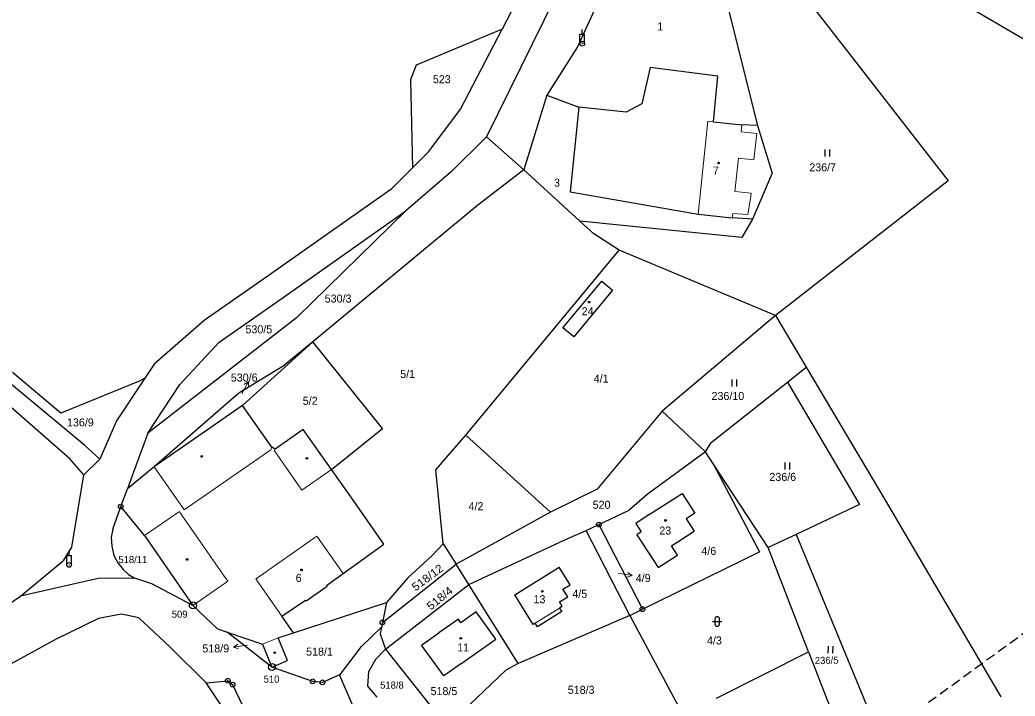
# Model space of a CAD drawing. Extents: x -885985 to -883535, y -1030025 to -1027941.
# Drawn here: x -884740.1 to -884528.7, y -1028443.4 to -1028299.8 of the extents above; entities that cross this region are included whole.
import ezdxf
from ezdxf.enums import TextEntityAlignment as Align

# ---------------------------------------------------------------- set-up
doc = ezdxf.new("R2010")
doc.units = 0
doc.header["$LTSCALE"] = 0.68
doc.linetypes.add('MEDIUM_DASHED', pattern=[4.5, 3, -1.5])
for name, color, linetype, lineweight in [('1', 7, 'Continuous', 25), ('13', 7, 'Continuous', 13), ('3', 7, 'Continuous', 25), ('4', 7, 'Continuous', 13), ('5', 7, 'Continuous', 25), ('6', 7, 'Continuous', 25), ('7', 7, 'Continuous', 13), ('8', 7, 'Continuous', 25)]:
    doc.layers.add(name, color=color, linetype=linetype, lineweight=lineweight)
doc.layers.add('2', color=7, linetype='Continuous')

msp = doc.modelspace()

# ---------------------------------------------------------------- linework, layer by layer
at = {"layer": '1'}
for p, q in [((-884601.9, -1028245.3), (-884640.99, -1028324.69)), ((-884598.34, -1028262.73), (-884542.88, -1028334.03)), ((-884598.34, -1028262.73), (-884583.43, -1028322.24)), ((-884606.99, -1028273.29), (-884621.63, -1028305.56)), ((-884512.54, -1028312.41), (-884580.94, -1028272.18)), ((-884635.61, -1028297.86), (-884637.65, -1028301.77)), ((-884637.65, -1028301.77), (-884655.9, -1028309.42)), ((-884646.51, -1028318.78), (-884637.65, -1028301.77)), ((-884621.63, -1028305.56), (-884628.2, -1028315.79)), ((-884655.9, -1028309.42), (-884657.11, -1028312.58)), ((-884606.23, -1028309.96), (-884607.96, -1028317.68)), ((-884591.81, -1028311.77), (-884606.23, -1028309.96)), ((-884592.79, -1028321.47), (-884591.81, -1028311.77)), ((-884657.11, -1028312.58), (-884656.72, -1028331.28)), ((-884628.2, -1028315.79), (-884633.08, -1028331.68)), ((-884628.2, -1028315.79), (-884621.35, -1028318.39)), ((-884607.96, -1028317.68), (-884611.34, -1028319.41)), ((-884653.26, -1028327.81), (-884646.51, -1028318.78)), ((-884621.35, -1028318.39), (-884623.24, -1028336.34)), ((-884611.34, -1028319.41), (-884621.35, -1028318.39)), ((-884592.79, -1028321.47), (-884586.72, -1028322.11)), ((-884583.43, -1028322.24), (-884586.72, -1028322.11)), ((-884583.43, -1028322.24), (-884580.27, -1028332.36)), ((-884640.99, -1028324.69), (-884648.41, -1028332.02)), ((-884640.99, -1028324.69), (-884633.08, -1028331.68)), ((-884656.72, -1028331.28), (-884653.26, -1028327.81)), ((-884656.72, -1028331.28), (-884661.3, -1028335.88)), ((-884648.41, -1028332.02), (-884658.14, -1028340.41)), ((-884633.08, -1028331.68), (-884642.8, -1028339.2)), ((-884621.16, -1028342.55), (-884633.08, -1028331.68)), ((-884580.27, -1028332.36), (-884584.5, -1028342.13)), ((-884542.88, -1028334.03), (-884577.06, -1028360.62)), ((-884661.3, -1028335.88), (-884687.36, -1028354.22)), ((-884623.24, -1028336.34), (-884596.04, -1028341.08)), ((-884642.8, -1028339.2), (-884677.87, -1028368.19)), ((-884684.16, -1028358.8), (-884658.14, -1028340.41)), ((-884658.14, -1028340.41), (-884681.31, -1028363.1)), ((-884596.04, -1028341.08), (-884588.76, -1028341.86)), ((-884618.17, -1028345.28), (-884621.16, -1028342.55)), ((-884586.71, -1028346.02), (-884621.16, -1028342.55)), ((-884584.5, -1028342.13), (-884588.76, -1028341.86)), ((-884584.5, -1028342.13), (-884586.71, -1028346.02)), ((-884612.79, -1028348.72), (-884618.17, -1028345.28)), ((-884645.35, -1028388.02), (-884612.79, -1028348.72)), ((-884579.61, -1028362.61), (-884612.79, -1028348.72)), ((-884729.52, -1028393.05), (-884772.29, -1028355.57)), ((-884687.36, -1028354.22), (-884700.95, -1028363.68)), ((-884726.38, -1028390.13), (-884763.34, -1028359.63)), ((-884697.76, -1028368.25), (-884684.16, -1028358.8)), ((-884577.06, -1028360.62), (-884579.61, -1028362.61)), ((-884681.31, -1028363.1), (-884712.92, -1028387.6)), ((-884700.95, -1028363.68), (-884711.6, -1028372.97)), ((-884579.61, -1028362.61), (-884603.68, -1028382.96)), ((-884579.61, -1028362.61), (-884573.11, -1028373.62)), ((-884706.14, -1028377.29), (-884697.76, -1028368.25)), ((-884677.87, -1028368.19), (-884692.81, -1028381.71)), ((-884677.87, -1028368.19), (-884684.17, -1028373.4)), ((-884663.05, -1028386.59), (-884677.87, -1028368.19)), ((-884711.6, -1028372.97), (-884713.58, -1028375.93)), ((-884731.39, -1028383.37), (-884741.68, -1028374.7)), ((-884684.17, -1028373.4), (-884693.57, -1028379.12)), ((-884577.07, -1028376.76), (-884573.11, -1028373.62)), ((-884573.11, -1028373.62), (-884556.32, -1028401.83)), ((-884714.57, -1028376.52), (-884731.39, -1028383.37)), ((-884713.58, -1028375.93), (-884719.6, -1028384.95)), ((-884713.58, -1028375.93), (-884714.57, -1028376.52)), ((-884712.92, -1028387.6), (-884706.14, -1028377.29)), ((-884593.29, -1028389.56), (-884577.07, -1028376.76)), ((-884577.07, -1028376.76), (-884561.72, -1028402.78)), ((-884693.57, -1028379.12), (-884711.56, -1028394.75)), ((-884692.81, -1028381.71), (-884711.56, -1028394.75)), ((-884686.56, -1028390.59), (-884692.81, -1028381.71)), ((-884603.68, -1028382.96), (-884617.46, -1028399.52)), ((-884603.68, -1028382.96), (-884594.47, -1028391.59)), ((-884719.6, -1028384.95), (-884723.14, -1028393.15)), ((-884712.92, -1028387.6), (-884715.98, -1028395.85)), ((-884679.9, -1028386.82), (-884685.85, -1028391)), ((-884673.9, -1028395.32), (-884679.9, -1028386.82)), ((-884673.9, -1028395.32), (-884663.05, -1028386.59)), ((-884651.75, -1028395.4), (-884645.35, -1028388.02)), ((-884627.36, -1028404.37), (-884645.35, -1028388.02)), ((-884594.47, -1028391.59), (-884593.29, -1028389.56)), ((-884723.14, -1028393.15), (-884726.38, -1028390.13)), ((-884685.85, -1028391), (-884686.56, -1028390.59)), ((-884594.47, -1028391.59), (-884606.87, -1028400.64)), ((-884592.87, -1028393.98), (-884594.47, -1028391.59)), ((-884726.51, -1028396.43), (-884729.52, -1028393.05)), ((-884726.51, -1028396.43), (-884723.14, -1028393.15)), ((-884592.87, -1028393.98), (-884582.99, -1028412.79)), ((-884581.14, -1028411.9), (-884592.87, -1028393.98)), ((-884711.56, -1028394.75), (-884717.22, -1028399.45)), ((-884715.98, -1028395.85), (-884717.22, -1028399.45)), ((-884669.56, -1028401.43), (-884673.9, -1028395.32)), ((-884650.17, -1028411.13), (-884651.75, -1028395.4)), ((-884729.05, -1028411.79), (-884726.51, -1028396.43)), ((-884718.69, -1028403.2), (-884717.22, -1028399.45)), ((-884617.46, -1028399.52), (-884627.36, -1028404.37)), ((-884606.41, -1028404.89), (-884599.43, -1028400.4)), ((-884599.43, -1028400.4), (-884596.7, -1028404.59)), ((-884662.81, -1028411.16), (-884669.56, -1028401.43)), ((-884606.87, -1028400.64), (-884610.68, -1028403.94)), ((-884556.32, -1028401.83), (-884531.74, -1028443.62)), ((-884720.39, -1028408), (-884718.69, -1028403.2)), ((-884713.65, -1028409.3), (-884718.69, -1028403.2)), ((-884627.36, -1028404.37), (-884647.46, -1028415.4)), ((-884617.1, -1028407), (-884610.68, -1028403.94)), ((-884596.7, -1028404.59), (-884598.57, -1028405.79)), ((-884561.72, -1028402.78), (-884575.21, -1028409.11)), ((-884606.41, -1028404.89), (-884609.29, -1028406.78)), ((-884598.57, -1028405.79), (-884596.87, -1028408.41)), ((-884720.39, -1028408), (-884720.73, -1028409.7)), ((-884624.31, -1028410.29), (-884619.81, -1028408.29)), ((-884619.81, -1028408.29), (-884617.1, -1028407)), ((-884610.56, -1028426.3), (-884619.81, -1028408.29)), ((-884617.1, -1028407), (-884607.86, -1028424.98)), ((-884601.68, -1028411.55), (-884596.87, -1028408.41)), ((-884720.73, -1028409.7), (-884720.6, -1028411.62)), ((-884713.65, -1028409.3), (-884703.35, -1028424.17)), ((-884671.43, -1028417.39), (-884662.81, -1028411.16)), ((-884650.17, -1028411.13), (-884652.63, -1028413.64)), ((-884650.17, -1028411.13), (-884647.46, -1028415.4)), ((-884644.72, -1028419.71), (-884624.31, -1028410.29)), ((-884609.02, -1028409.16), (-884604.48, -1028416.15)), ((-884575.21, -1028409.11), (-884581.14, -1028411.9)), ((-884575.21, -1028409.11), (-884553.2, -1028462.33)), ((-884730.78, -1028414.56), (-884729.05, -1028411.79)), ((-884720.6, -1028411.62), (-884720.17, -1028413.58)), ((-884607.86, -1028424.98), (-884582.99, -1028412.79)), ((-884600.42, -1028413.5), (-884601.68, -1028411.55)), ((-884572.61, -1028434.07), (-884581.14, -1028411.9)), ((-884739.96, -1028422.25), (-884730.78, -1028414.56)), ((-884720.17, -1028413.58), (-884719.3, -1028415.16)), ((-884719.3, -1028415.16), (-884718.16, -1028416.55)), ((-884663.08, -1028427.79), (-884647.46, -1028415.4)), ((-884652.63, -1028413.64), (-884657.67, -1028418.33)), ((-884644.72, -1028419.71), (-884647.46, -1028415.4)), ((-884604.48, -1028416.15), (-884600.42, -1028413.5)), ((-884718.16, -1028416.55), (-884717.04, -1028417.61)), ((-884674.99, -1028419.92), (-884671.43, -1028417.39)), ((-884634.99, -1028421.96), (-884625.53, -1028416.09)), ((-884623.24, -1028419.78), (-884625.53, -1028416.09)), ((-884723.5, -1028418.44), (-884739.96, -1028422.25)), ((-884715.7, -1028418.43), (-884723.5, -1028418.44)), ((-884717.04, -1028417.61), (-884715.7, -1028418.43)), ((-884712.1, -1028419.58), (-884715.7, -1028418.43)), ((-884703.35, -1028424.17), (-884712.1, -1028419.58)), ((-884657.67, -1028418.33), (-884662.22, -1028423.53)), ((-884679.31, -1028423.19), (-884674.84, -1028420.07)), ((-884674.84, -1028420.07), (-884674.99, -1028419.92)), ((-884662.42, -1028433.46), (-884644.72, -1028419.71)), ((-884634.26, -1028436.55), (-884644.72, -1028419.71)), ((-884624.75, -1028420.72), (-884623.24, -1028419.78)), ((-884623.72, -1028422.36), (-884624.75, -1028420.72)), ((-884750, -1028428.98), (-884739.96, -1028422.25)), ((-884684.45, -1028426.49), (-884679.42, -1028423.04)), ((-884681.98, -1028430.02), (-884662.22, -1028423.53)), ((-884679.42, -1028423.04), (-884679.31, -1028423.19)), ((-884631.04, -1028428.22), (-884634.99, -1028421.96)), ((-884625.46, -1028423.45), (-884623.72, -1028422.36)), ((-884624.88, -1028424.38), (-884625.46, -1028423.45)), ((-884703.35, -1028424.17), (-884698.1, -1028429.13)), ((-884643.17, -1028425.52), (-884646.46, -1028427.89)), ((-884639, -1028431.37), (-884643.17, -1028425.52)), ((-884624.98, -1028425.5), (-884630.13, -1028428.72)), ((-884624.88, -1028424.38), (-884625.45, -1028424.74)), ((-884625.45, -1028424.74), (-884624.98, -1028425.5)), ((-884610.56, -1028426.3), (-884607.86, -1028424.98)), ((-884723.41, -1028426.93), (-884732.52, -1028431.41)), ((-884718.51, -1028426.06), (-884723.41, -1028426.93)), ((-884714.87, -1028426.79), (-884718.51, -1028426.06)), ((-884708.28, -1028433), (-884714.87, -1028426.79)), ((-884681.98, -1028430.02), (-884684.45, -1028426.49)), ((-884646.96, -1028427.11), (-884651.09, -1028430.02)), ((-884646.46, -1028427.89), (-884646.96, -1028427.11)), ((-884610.56, -1028426.3), (-884634.26, -1028436.55)), ((-884630.61, -1028427.95), (-884631.04, -1028428.22)), ((-884630.13, -1028428.72), (-884630.61, -1028427.95)), ((-884610.56, -1028426.3), (-884599.2, -1028447.46)), ((-884698.1, -1028429.13), (-884696.09, -1028429.83)), ((-884696.09, -1028429.83), (-884688.56, -1028432.44)), ((-884686.55, -1028437.28), (-884696.09, -1028429.83)), ((-884685.26, -1028431.1), (-884681.98, -1028430.02)), ((-884667.55, -1028432.9), (-884663.28, -1028428.77)), ((-884663.28, -1028428.77), (-884663.58, -1028430.24)), ((-884732.52, -1028431.41), (-884743.63, -1028437.5)), ((-884683.25, -1028435.9), (-884685.26, -1028431.1)), ((-884663.58, -1028430.24), (-884662.42, -1028433.46)), ((-884646.42, -1028436.6), (-884639, -1028431.37)), ((-884700.53, -1028440.64), (-884708.28, -1028433)), ((-884688.56, -1028432.44), (-884686.55, -1028437.28)), ((-884671.97, -1028438.76), (-884667.55, -1028432.9)), ((-884662.42, -1028433.46), (-884664.59, -1028435.64)), ((-884662.42, -1028433.46), (-884651.31, -1028447.47)), ((-884592.12, -1028443.9), (-884572.61, -1028434.07)), ((-884572.61, -1028434.07), (-884560.14, -1028466.04)), ((-884686.55, -1028437.28), (-884683.25, -1028435.9)), ((-884664.59, -1028435.64), (-884666.07, -1028438.3)), ((-884634.26, -1028436.55), (-884636.88, -1028437.92)), ((-884677.9, -1028440.31), (-884686.55, -1028437.28)), ((-884666.07, -1028438.3), (-884666.24, -1028441.34)), ((-884636.88, -1028437.92), (-884648.77, -1028449.22)), ((-884700.53, -1028440.64), (-884695.94, -1028440.19)), ((-884681.12, -1028469.67), (-884700.53, -1028440.64)), ((-884695.94, -1028440.19), (-884694.93, -1028441.01)), ((-884675.84, -1028440.52), (-884677.9, -1028440.31)), ((-884672.22, -1028438.93), (-884675.84, -1028440.52)), ((-884672.22, -1028438.93), (-884671.97, -1028438.76)), ((-884668.71, -1028446.95), (-884672.22, -1028438.93)), ((-884694.93, -1028441.01), (-884688.38, -1028454.57)), ((-884666.24, -1028441.34), (-884664.31, -1028443.64))]:
    msp.add_line(p, q, dxfattribs=at)
msp.add_lwpolyline([(-884624.75, -1028365.26), (-884616.46, -1028355.3), (-884614.19, -1028357.22), (-884622.46, -1028367.16)], close=True, dxfattribs=at)
for points in [[(-884609.29, -1028406.78), (-884608.16, -1028408.54), (-884609.02, -1028409.16)], [(-884662.22, -1028423.53), (-884663.08, -1028427.79), (-884663.28, -1028428.77)], [(-884646.42, -1028436.6), (-884650.07, -1028439.14), (-884654.76, -1028432.63), (-884651.09, -1028430.02)]]:
    msp.add_lwpolyline(points, dxfattribs=at)
at = {"layer": '13'}
msp.add_lwpolyline([(-884617.1, -1028407), (-884619.81, -1028408.29), (-884610.56, -1028426.3), (-884607.86, -1028424.98)], close=True, dxfattribs=at)
at = {"layer": '3'}
for p, q in [((-884569.021, -1028328.86), (-884569.021, -1028327.36)), ((-884568.02, -1028328.86), (-884568.02, -1028327.36)), ((-884588.801, -1028377.68), (-884588.801, -1028376.18)), ((-884587.8, -1028377.68), (-884587.8, -1028376.18)), ((-884577.571, -1028395.3), (-884577.571, -1028393.8)), ((-884576.57, -1028395.3), (-884576.57, -1028393.8)), ((-884592.961, -1028427.601), (-884590.959, -1028427.601)), ((-884592.461, -1028427.101), (-884592.461, -1028428.102)), ((-884591.459, -1028428.102), (-884591.459, -1028427.101)), ((-884568.391, -1028434.311), (-884568.365, -1028432.811)), ((-884567.39, -1028434.329), (-884567.364, -1028432.829))]:
    msp.add_line(p, q, dxfattribs=at)
for centre, start, end in [((-884591.96, -1028427.1009), 0, 180), ((-884591.96, -1028428.1009), 180, 359.98789)]:
    msp.add_arc(centre, 0.5, start, end, dxfattribs=at)
at = {"layer": '4'}
for p, q in [((-884596.04, -1028341.08), (-884593.99, -1028321.34)), ((-884593.99, -1028321.34), (-884592.79, -1028321.47)), ((-884586.72, -1028322.11), (-884586.88, -1028323.6)), ((-884586.88, -1028323.6), (-884583.55, -1028323.94)), ((-884583.55, -1028323.94), (-884584.18, -1028329.55)), ((-884587.46, -1028329.21), (-884588.2, -1028336.31)), ((-884584.18, -1028329.55), (-884587.46, -1028329.21)), ((-884588.2, -1028336.31), (-884584.77, -1028336.66)), ((-884584.77, -1028336.66), (-884584.86, -1028337.24)), ((-884584.86, -1028337.24), (-884585.46, -1028341.17)), ((-884588.68, -1028340.92), (-884588.76, -1028341.86)), ((-884585.46, -1028341.17), (-884588.68, -1028340.92)), ((-884705.18, -1028403.88), (-884686.82, -1028391.11)), ((-884686.82, -1028391.11), (-884686.56, -1028390.59)), ((-884686.05, -1028391.38), (-884685.85, -1028391)), ((-884686.05, -1028391.38), (-884680.18, -1028399.72)), ((-884711.56, -1028394.75), (-884705.37, -1028403.64)), ((-884680.18, -1028399.72), (-884673.9, -1028395.32)), ((-884706.23, -1028404.23), (-884713.65, -1028409.3)), ((-884705.37, -1028403.64), (-884705.18, -1028403.88)), ((-884676.99, -1028409.5), (-884689.81, -1028418.44)), ((-884676.99, -1028409.5), (-884671.43, -1028417.39)), ((-884696.19, -1028419.22), (-884703.35, -1028424.17)), ((-884695.93, -1028419.05), (-884696.33, -1028418.47)), ((-884696.19, -1028419.22), (-884695.93, -1028419.05)), ((-884689.81, -1028418.44), (-884689.98, -1028418.56)), ((-884689.98, -1028418.56), (-884689.72, -1028418.94)), ((-884689.72, -1028418.94), (-884684.45, -1028426.49)), ((-884630.61, -1028427.95), (-884625.45, -1028424.74)), ((-884688.56, -1028432.44), (-884685.26, -1028431.1))]:
    msp.add_line(p, q, dxfattribs=at)
msp.add_lwpolyline([(-884696.33, -1028418.47), (-884706.04, -1028404.52), (-884706.23, -1028404.23)], dxfattribs=at)
at = {"layer": '5'}
for centre in [(-884591.6768, -1028330.2392), (-884619.1668, -1028359.7792), (-884701.4768, -1028392.5492), (-884679.1368, -1028392.9592), (-884602.9468, -1028406.1392), (-884704.5868, -1028414.4292), (-884680.2868, -1028416.6392), (-884629.1268, -1028421.1892), (-884646.4468, -1028431.1592), (-884685.9968, -1028434.2292)]:
    msp.add_circle(centre, 0.175, dxfattribs=at)
at = {"layer": '6'}
for p, q in [((-884621.13, -1028302.886), (-884620.13, -1028302.886)), ((-884621.13, -1028304.886), (-884621.13, -1028302.886)), ((-884620.63, -1028302.886), (-884620.63, -1028301.886)), ((-884620.13, -1028304.886), (-884620.13, -1028302.886)), ((-884729.65, -1028413.586), (-884729.65, -1028412.586)), ((-884730.15, -1028413.586), (-884729.15, -1028413.586)), ((-884730.15, -1028415.586), (-884730.15, -1028413.586)), ((-884729.15, -1028415.586), (-884729.15, -1028413.586))]:
    msp.add_line(p, q, dxfattribs=at)
at = {"layer": '6', "linetype": 'MEDIUM_DASHED'}
msp.add_line((-884498.42, -1028409.47), (-884561.98, -1028455.63), dxfattribs=at)
at = {"layer": '6'}
for centre, radius in [((-884620.63, -1028304.8876), 0.5), ((-884620.63, -1028304.8876), 0.0303), ((-884729.65, -1028415.5876), 0.5), ((-884729.65, -1028415.5876), 0.0303)]:
    msp.add_circle(centre, radius, dxfattribs=at)
at = {"layer": '7'}
for p, q in [((-884691.541, -1028376.61), (-884692.453, -1028377.259)), ((-884610.016, -1028417.819), (-884610.927, -1028417.168)), ((-884694.742, -1028433.028), (-884693.68, -1028433.384))]:
    msp.add_line(p, q, dxfattribs=at)
for points in [[(-884692.95, -1028379.26), (-884691.541, -1028376.61), (-884691.569, -1028377.73)], [(-884612.98, -1028417.35), (-884610.016, -1028417.819), (-884611.083, -1028418.157)], [(-884691.77, -1028432.61), (-884694.742, -1028433.028), (-884693.82, -1028432.392)]]:
    msp.add_lwpolyline(points, dxfattribs=at)
at = {"layer": '8'}
for centre, radius in [((-884718.69, -1028403.1999), 0.5), ((-884718.69, -1028403.1999), 0.0303), ((-884617.1, -1028406.9999), 0.5), ((-884617.1, -1028406.9999), 0.0303), ((-884703.35, -1028424.1698), 0.75), ((-884703.35, -1028424.1698), 0.03), ((-884607.86, -1028424.9799), 0.5), ((-884607.86, -1028424.9799), 0.0303), ((-884663.08, -1028427.7899), 0.5), ((-884663.08, -1028427.7899), 0.0303), ((-884686.54, -1028437.2598), 0.75), ((-884686.54, -1028437.2598), 0.03), ((-884695.94, -1028440.1899), 0.5), ((-884695.94, -1028440.1899), 0.0303), ((-884694.93, -1028441.0099), 0.5), ((-884677.9, -1028440.3099), 0.5), ((-884677.9, -1028440.3099), 0.0303), ((-884675.84, -1028440.5199), 0.5), ((-884675.84, -1028440.5199), 0.0303), ((-884694.93, -1028441.0099), 0.0303)]:
    msp.add_circle(centre, radius, dxfattribs=at)

# ---------------------------------------------------------------- texts
at = {"layer": '2'}
for s, height, p in [('1', 1.7, (-884604.7, -1028302.075)), ('523', 1.7, (-884652.38, -1028313.285)), ('236/7', 1.7, (-884572.42, -1028331.995)), ('7', 1.7, (-884592.89, -1028332.675)), ('3', 1.7, (-884626.65, -1028335.255)), ('530/3', 1.7, (-884675.35, -1028359.865)), ('530/5', 1.7, (-884692.19, -1028366.395)), ('5/1', 1.7, (-884659.32, -1028375.875)), ('4/1', 1.7, (-884618.2, -1028376.855)), ('236/10', 1.7, (-884593.18, -1028380.555)), ('5/2', 1.7, (-884680.02, -1028381.575)), ('136/9', 1.7, (-884730.1, -1028386.165)), ('236/6', 1.7, (-884580.89, -1028397.735)), ('4/2', 1.7, (-884644.8, -1028403.965)), ('520', 1.7, (-884618.43, -1028403.665)), ('23', 1.7, (-884604.27, -1028409.125)), ('4/6', 1.7, (-884595.33, -1028413.455)), ('518/11', 1.5, (-884719.18, -1028415.195)), ('6', 1.7, (-884681.52, -1028419.185)), ('4/9', 1.7, (-884609.27, -1028419.212)), ('4/5', 1.7, (-884622.75, -1028422.555)), ('13', 1.7, (-884631, -1028423.715)), ('11', 1.7, (-884647.21, -1028433.965)), ('4/3', 1.7, (-884594.15, -1028432.475)), ('518/1', 1.7, (-884679.3, -1028434.845)), ('518/8', 1.5, (-884663.58, -1028441.855)), ('518/5', 1.7, (-884652.87, -1028443.235)), ('518/3', 1.7, (-884623.72, -1028442.955))]:
    msp.add_text(s, height=height, dxfattribs=at).set_placement(p)
for s, p in [('24', (-884619.499, -1028362.555)), ('530/6', (-884692.45, -1028376.645)), ('518/9', (-884698.5, -1028434.165))]:
    msp.add_text(s, height=1.7, dxfattribs=at).set_placement(p, align=Align.CENTER)
at = {"layer": '2', "width": 1.1}
msp.add_text('518/12', height=1.7, rotation=37, dxfattribs=at).set_placement((-884653.013, -1028418.9325), align=Align.CENTER)
msp.add_text('518/4', height=1.7, rotation=39, dxfattribs=at).set_placement((-884652.822, -1028425.3))
at = {"layer": '2'}
msp.add_text('236/5', height=1.5, rotation=1, dxfattribs=at).set_placement((-884571.223, -1028436.634))
at = {"layer": '8'}
for s, p in [('509', (-884704.492, -1028426.803)), ('510', (-884684.972, -1028440.583))]:
    msp.add_text(s, height=1.5, dxfattribs=at).set_placement(p, align=Align.RIGHT)

doc.saveas('drawing.dxf')
